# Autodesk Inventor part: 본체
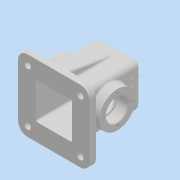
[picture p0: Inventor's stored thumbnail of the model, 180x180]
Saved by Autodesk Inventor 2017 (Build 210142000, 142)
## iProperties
Part Number: 본체
Material: 일반
Document SubType Name: Modeling
Designer: MRC
Density: 1 g/cm^3
Appearance: 기본값
Author: MRC
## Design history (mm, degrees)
sketch "스케치1"
  geometry: L1 (-34, -34)-(34, -34); L2 (34, -34)-(34, 34); L3 (34, 34)-(-34, 34); L4 (-34, 34)-(-34, -34); L5 (-34, -34)-(34, 34); L6 (34, -34)-(-34, 34); 1 further point
  constraints: 12 end point, 2 midpoint, 2 parallel, 1 horizontal, 1 perpendicular
  dimensions: "d0" = 68 distance of L3.end L2.end; "d1" = 68 distance of L2.end L1.end
extrude "돌출1" new body sketch "스케치1" distance "d2" = 53; taper "d4" = 0 deg; dims "d3" = 52, "d5" = 0
fillet "모깎기1" dims "d6" = 8
fillet "모깎기2" dims "d7" = 8
feature "쉘1" dims "d8" = 5
node "작업 평면1"
sketch "스케치2"
  geometry: C1 r 28.5 at (0, 0); 1 further point
  constraints: 1 centre point, 1 coincident
  dimensions: "d10" = 57 diameter of C1
extrude "돌출2" join sketch "스케치2" stored distance "d11" = 53; taper "d12" = 0 deg
fillet "모깎기3" dims "d13" = 3
hole "구멍1" diameter "d16" = 30; stored, may be unused: countersink angle "d20" = 90 deg, drill point angle "d22" = 118 deg; dims "d14" = 10, "d15" = 10, "d17" = 6, "d18" = 35, "d19" = 17, "d21" = 8
sketch "스케치3"
  geometry: C1 r 17.5 at (0, 0) reference; 1 further point
  constraints: 1 vertical alignment
  dimensions: "d23" = 22 distance of point (0, 22) C1.centre
hole "구멍2" sketch "스케치3" at (0, 22) diameter "d24" = 3.242; stored, may be unused: countersink angle "d28" = 90 deg, drill point angle "d30" = 118 deg; dims "d25" = 8, "d26" = 35, "d27" = 17, "d29" = 10
fillet "모깎기4" dims "d34" = 3
sketch "스케치4"
  geometry: C1 r 20 at (0, 0); 1 further point
  constraints: 1 centre point, 1 coincident
  dimensions: "d35" = 40 diameter of C1
extrude "돌출3" join sketch "스케치4" distance "d36" = 10; taper "d37" = 0 deg
hole "구멍3" diameter "d40" = 22.835; stored, may be unused: countersink angle "d44" = 90 deg, drill point angle "d46" = 118 deg; dims "d38" = 10, "d39" = 10, "d41" = 50, "d42" = 35, "d43" = 17, "d45" = 59.3
feature "면 기울기1" dims angle "d47" = 8 deg
sketch "스케치5"
  geometry: L1 (-26, -34)-(26, -34) reference; L2 (34, -26)-(34, 26) reference; L3 (26, 34)-(-26, 34) reference; L4 (-34, 26)-(-34, -26) reference; L5 (-57, 57)-(57, 57); L6 (57, 57)-(57, -57); L7 (57, -57)-(-57, -57); L8 (-57, -57)-(-57, 57); L9 (-57, 57)-(57, -57); L10 (57, 57)-(-57, -57); A1 r 8 centre (-26, -26) between (-34, -26) and (-26, -34) reference; A2 r 8 centre (26, -26) between (26, -34) and (34, -26) reference; A3 r 8 centre (26, 26) between (34, 26) and (26, 34) reference; A4 r 8 centre (-26, 26) between (-26, 34) and (-34, 26) reference; 1 further point
  constraints: 12 end point, 2 midpoint, 2 parallel, 1 horizontal, 1 perpendicular
  dimensions: "d48" = 114 distance of L6.end L7.end; "d49" = 114 distance of L5.end L6.end
extrude "돌출4" join sketch "스케치5" distance "d50" = 10; taper "d51" = 0 deg
fillet "모깎기5" dims "d52" = 15
sketch "스케치6"
  geometry: A1 r 15 centre (42, 42) between (57, 42) and (42, 57) reference; A2 r 15 centre (-42, 42) between (-42, 57) and (-57, 42) reference; A3 r 15 centre (-42, -42) between (-57, -42) and (-42, -57) reference; A4 r 15 centre (42, -42) between (42, -57) and (57, -42) reference; 5 further points
  constraints: 4 coincident
hole "구멍4" sketch "스케치6" at (-42, 42), (42, 42), (42, -42), (-42, -42) diameter "d53" = 10; stored, may be unused: countersink angle "d57" = 90 deg, drill point angle "d59" = 118 deg; dims "d54" = 50, "d55" = 18, "d56" = 2, "d58" = 59.3
sketch "스케치7"
  geometry: L1 (-29.986, -46.882)-(-42, -49); L2 (-42, -42)-(-42, -57) reference; L3 (-42, -57)-(-52, -57) reference; 1 further point
  constraints: 2 end point, 1 point on line
  dimensions: "d60" = 8 distance of L1.end L2.end; "d61" = 10 deg angle of L1 L3
feature "리브1" sketch "스케치7" dims "d62" = 1, "d63" = 10, "d64" = 0, "d65" = 0, "d66" = 1, "d67" = 1
fillet "모깎기6" dims "d68" = 3
fillet "모깎기7" dims "d69" = 3
fillet "모깎기8" dims "d70" = 3
fillet "모깎기9" dims "d71" = 0.3
chamfer "모따기1" distance "d72" = 1; stored, may be unused: second distance "d73" = 2, angle "d74" = 45 deg
chamfer "모따기2" distance "d75" = 1; stored, may be unused: second distance "d76" = 2, angle "d77" = 45 deg
fillet "모깎기10" dims "d78" = 3
node "작업 평면2"
sketch "스케치8"
  geometry: L1 (45, 34)-(-39, 34) reference; L2 (63, -20)-(63, 20) reference; 2 further points
  constraints: 1 other
  dimensions: "d80" = 34 distance from line of point (38, 0) L1; "d81" = 25 distance from line of point (38, 0) L2
feature "엠보싱1" sketch "스케치8" dims "d0" = 68, "d1" = 68, "d82" = 0.5, "d83" = 0
node "솔리드1"
pattern_circular "원형 패턴1" dims angle "d32" = 360 deg
mirror "미러1"
mirror "미러2"
other parameters: "d9" = 49, "d79" = 59
